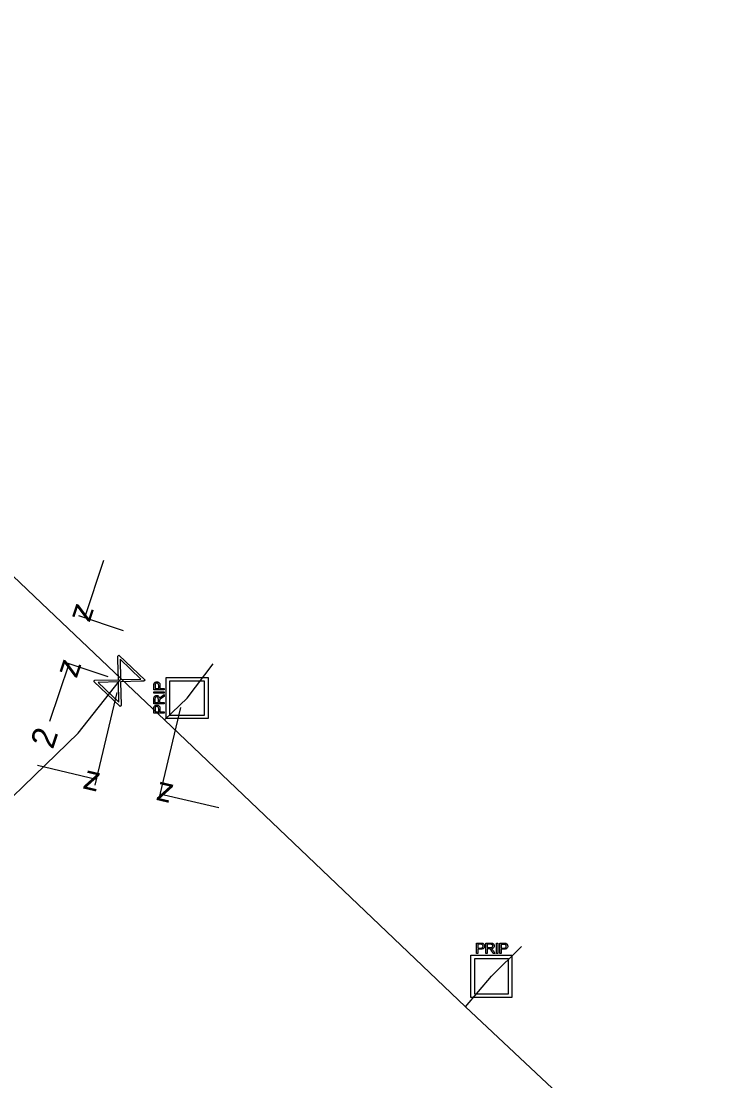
# Model space of a CAD drawing. Extents: x -643842 to -636370, y -1119190 to -1110210.
# Drawn here: x -642410.27 to -642380.97, y -1113929.96 to -1113886.16 of the extents above; entities that cross this region are included whole.
import ezdxf

# ---------------------------------------------------------------- set-up
doc = ezdxf.new("R2010")
doc.units = 0
for name, color, linetype in [('Default', 7, 'Continuous'), ('Level 10', 7, 'Continuous'), ('Level 16', 7, 'Continuous'), ('Level 18', 7, 'Continuous'), ('Level 21', 7, 'Continuous'), ('Level 23', 7, 'Continuous')]:
    doc.layers.add(name, color=color, linetype=linetype)

msp = doc.modelspace()

# ---------------------------------------------------------------- linework, layer by layer
at = {"layer": 'Default'}
for points in [[(-642404.79, -1113913.633), (-642404.79, -1113913.591), (-642404.785, -1113913.567), (-642404.779, -1113913.536), (-642404.765, -1113913.515), (-642404.75, -1113913.493), (-642404.724, -1113913.48), (-642404.697, -1113913.468), (-642404.665, -1113913.468), (-642404.609, -1113913.468), (-642404.572, -1113913.502), (-642404.535, -1113913.536), (-642404.535, -1113913.627)], [(-642404.584, -1113913.627), (-642404.584, -1113913.572), (-642404.605, -1113913.549), (-642404.625, -1113913.526), (-642404.664, -1113913.526), (-642404.69, -1113913.526), (-642404.709, -1113913.539), (-642404.728, -1113913.553), (-642404.734, -1113913.575), (-642404.738, -1113913.589), (-642404.738, -1113913.629)], [(-642404.791, -1113914.182), (-642404.791, -1113914.125), (-642404.779, -1113914.095), (-642404.768, -1113914.065), (-642404.738, -1113914.048), (-642404.709, -1113914.03), (-642404.674, -1113914.03), (-642404.627, -1113914.03), (-642404.596, -1113914.059), (-642404.565, -1113914.089), (-642404.557, -1113914.15), (-642404.545, -1113914.128), (-642404.535, -1113914.117), (-642404.513, -1113914.092), (-642404.478, -1113914.07)], [(-642404.601, -1113914.194), (-642404.601, -1113914.155), (-642404.609, -1113914.133), (-642404.617, -1113914.111), (-642404.634, -1113914.1), (-642404.652, -1113914.089), (-642404.674, -1113914.089), (-642404.703, -1113914.089), (-642404.723, -1113914.111), (-642404.743, -1113914.133), (-642404.743, -1113914.181)], [(-642404.45, -1113914.122), (-642404.489, -1113914.147), (-642404.51, -1113914.163), (-642404.53, -1113914.18), (-642404.538, -1113914.193), (-642404.546, -1113914.206), (-642404.549, -1113914.219), (-642404.552, -1113914.228), (-642404.552, -1113914.25)], [(-642404.791, -1113914.596), (-642404.791, -1113914.553), (-642404.787, -1113914.53), (-642404.781, -1113914.499), (-642404.766, -1113914.477), (-642404.751, -1113914.455), (-642404.725, -1113914.442), (-642404.699, -1113914.43), (-642404.667, -1113914.43), (-642404.611, -1113914.43), (-642404.573, -1113914.464), (-642404.536, -1113914.499), (-642404.536, -1113914.59)], [(-642404.586, -1113914.59), (-642404.586, -1113914.534), (-642404.606, -1113914.511), (-642404.627, -1113914.489), (-642404.665, -1113914.489), (-642404.691, -1113914.489), (-642404.71, -1113914.502), (-642404.73, -1113914.515), (-642404.735, -1113914.537), (-642404.74, -1113914.552), (-642404.74, -1113914.591)], [(-642391.283, -1113924.264), (-642391.24, -1113924.264), (-642391.217, -1113924.268), (-642391.186, -1113924.274), (-642391.164, -1113924.289), (-642391.142, -1113924.304), (-642391.129, -1113924.33), (-642391.117, -1113924.356), (-642391.117, -1113924.388), (-642391.117, -1113924.444), (-642391.151, -1113924.482), (-642391.186, -1113924.519), (-642391.277, -1113924.519)], [(-642391.277, -1113924.469), (-642391.221, -1113924.469), (-642391.198, -1113924.449), (-642391.176, -1113924.428), (-642391.176, -1113924.39), (-642391.176, -1113924.364), (-642391.189, -1113924.345), (-642391.202, -1113924.326), (-642391.224, -1113924.32), (-642391.239, -1113924.315), (-642391.278, -1113924.315)], [(-642390.809, -1113924.605), (-642390.834, -1113924.566), (-642390.85, -1113924.545), (-642390.867, -1113924.525), (-642390.88, -1113924.517), (-642390.893, -1113924.509), (-642390.906, -1113924.506), (-642390.915, -1113924.503), (-642390.937, -1113924.503)], [(-642390.881, -1113924.454), (-642390.842, -1113924.454), (-642390.82, -1113924.446), (-642390.798, -1113924.438), (-642390.787, -1113924.421), (-642390.776, -1113924.403), (-642390.776, -1113924.381), (-642390.776, -1113924.352), (-642390.798, -1113924.332), (-642390.82, -1113924.312), (-642390.868, -1113924.312)], [(-642390.869, -1113924.264), (-642390.812, -1113924.264), (-642390.782, -1113924.276), (-642390.752, -1113924.287), (-642390.735, -1113924.317), (-642390.717, -1113924.346), (-642390.717, -1113924.381), (-642390.717, -1113924.428), (-642390.746, -1113924.459), (-642390.776, -1113924.49), (-642390.837, -1113924.498), (-642390.815, -1113924.51), (-642390.804, -1113924.52), (-642390.779, -1113924.542), (-642390.757, -1113924.577)], [(-642390.32, -1113924.265), (-642390.278, -1113924.265), (-642390.254, -1113924.27), (-642390.223, -1113924.276), (-642390.202, -1113924.29), (-642390.18, -1113924.305), (-642390.167, -1113924.331), (-642390.155, -1113924.358), (-642390.155, -1113924.39), (-642390.155, -1113924.446), (-642390.189, -1113924.483), (-642390.223, -1113924.52), (-642390.314, -1113924.52)], [(-642390.314, -1113924.471), (-642390.259, -1113924.471), (-642390.236, -1113924.45), (-642390.213, -1113924.43), (-642390.213, -1113924.391), (-642390.213, -1113924.365), (-642390.226, -1113924.346), (-642390.24, -1113924.327), (-642390.262, -1113924.321), (-642390.276, -1113924.317), (-642390.316, -1113924.317)]]:
    msp.add_open_spline(points, degree=3, dxfattribs=at)
at = {"layer": 'Level 10'}
for points in [[(-642406.864, -1113908.452), (-642407.66, -1113910.822)], [(-642406.047, -1113911.364), (-642407.897, -1113910.742)], [(-642409.093, -1113915.089), (-642408.297, -1113912.719)], [(-642406.684, -1113913.261), (-642408.534, -1113912.64)], [(-642406.325, -1113913.907), (-642407.224, -1113917.731)], [(-642403.692, -1113914.526), (-642404.592, -1113918.351)], [(-642409.601, -1113916.915), (-642407.167, -1113917.488)], [(-642402.101, -1113918.68), (-642404.535, -1113918.107)]]:
    msp.add_lwpolyline(points, dxfattribs=at)
at = {"layer": 'Level 16'}
for points in [[(-642406.237, -1113912.36), (-642405.15, -1113913.394), (-642405.196, -1113913.441), (-642405.324, -1113913.44), (-642406.164, -1113913.463), (-642406.138, -1113914.433), (-642406.184, -1113914.481), (-642407.271, -1113913.447), (-642407.225, -1113913.399), (-642406.254, -1113913.377), (-642406.276, -1113912.537), (-642406.283, -1113912.408), (-642406.237, -1113912.36)], [(-642406.188, -1113912.536), (-642406.166, -1113913.375), (-642405.329, -1113913.353), (-642406.188, -1113912.536)], [(-642406.23, -1113914.308), (-642406.252, -1113913.465), (-642407.093, -1113913.487), (-642406.23, -1113914.308)]]:
    msp.add_lwpolyline(points, dxfattribs=at)
at = {"layer": 'Level 18'}
for points in [[(-642404.359, -1113913.794), (-642404.79, -1113913.794), (-642404.79, -1113913.633)], [(-642404.738, -1113913.629), (-642404.738, -1113913.739), (-642404.584, -1113913.739)], [(-642404.584, -1113913.739), (-642404.584, -1113913.627)], [(-642404.535, -1113913.627), (-642404.535, -1113913.739), (-642404.359, -1113913.739), (-642404.359, -1113913.794)], [(-642404.284, -1113913.292), (-642402.542, -1113913.292), (-642402.542, -1113914.988), (-642404.284, -1113914.988), (-642404.284, -1113913.292)], [(-642404.136, -1113914.843), (-642402.69, -1113914.843), (-642402.69, -1113913.437), (-642404.136, -1113913.437), (-642404.136, -1113914.843)], [(-642404.359, -1113913.936), (-642404.79, -1113913.936), (-642404.79, -1113913.881), (-642404.359, -1113913.881), (-642404.359, -1113913.936)], [(-642404.478, -1113914.07), (-642404.36, -1113913.995), (-642404.36, -1113914.067), (-642404.45, -1113914.122)], [(-642404.36, -1113914.373), (-642404.791, -1113914.373), (-642404.791, -1113914.182)], [(-642404.743, -1113914.181), (-642404.743, -1113914.316), (-642404.601, -1113914.316)], [(-642404.601, -1113914.316), (-642404.601, -1113914.194)], [(-642404.552, -1113914.25), (-642404.552, -1113914.316), (-642404.36, -1113914.316), (-642404.36, -1113914.373)], [(-642404.36, -1113914.757), (-642404.791, -1113914.757), (-642404.791, -1113914.596)], [(-642404.74, -1113914.591), (-642404.74, -1113914.701), (-642404.586, -1113914.701)], [(-642404.586, -1113914.701), (-642404.586, -1113914.59)], [(-642404.536, -1113914.59), (-642404.536, -1113914.701), (-642404.36, -1113914.701), (-642404.36, -1113914.757)], [(-642391.444, -1113924.695), (-642391.444, -1113924.264), (-642391.283, -1113924.264)], [(-642391.277, -1113924.519), (-642391.388, -1113924.519), (-642391.388, -1113924.695), (-642391.444, -1113924.695)], [(-642391.278, -1113924.315), (-642391.388, -1113924.315), (-642391.388, -1113924.469)], [(-642391.388, -1113924.469), (-642391.277, -1113924.469)], [(-642391.06, -1113924.695), (-642391.06, -1113924.264), (-642390.869, -1113924.264)], [(-642390.937, -1113924.503), (-642391.003, -1113924.503), (-642391.003, -1113924.695), (-642391.06, -1113924.695)], [(-642390.868, -1113924.312), (-642391.003, -1113924.312), (-642391.003, -1113924.454)], [(-642391.003, -1113924.454), (-642390.881, -1113924.454)], [(-642390.757, -1113924.577), (-642390.682, -1113924.695), (-642390.754, -1113924.695), (-642390.809, -1113924.605)], [(-642390.623, -1113924.696), (-642390.623, -1113924.265), (-642390.568, -1113924.265), (-642390.568, -1113924.696), (-642390.623, -1113924.696)], [(-642390.481, -1113924.696), (-642390.481, -1113924.265), (-642390.32, -1113924.265)], [(-642390.314, -1113924.52), (-642390.426, -1113924.52), (-642390.426, -1113924.696), (-642390.481, -1113924.696)], [(-642390.316, -1113924.317), (-642390.426, -1113924.317), (-642390.426, -1113924.471)], [(-642390.426, -1113924.471), (-642390.314, -1113924.471)], [(-642389.979, -1113924.771), (-642389.979, -1113926.513), (-642391.675, -1113926.513), (-642391.675, -1113924.771), (-642389.979, -1113924.771)], [(-642391.53, -1113924.919), (-642391.53, -1113926.365), (-642390.124, -1113926.365), (-642390.124, -1113924.919), (-642391.53, -1113924.919)]]:
    msp.add_lwpolyline(points, dxfattribs=at)
at = {"layer": 'Level 21'}
msp.add_lwpolyline([(-642434.757, -1113886.158), (-642434.32, -1113886.59), (-642432.757, -1113887.981), (-642428.894, -1113891.665), (-642427.355, -1113893.147), (-642421.665, -1113898.587), (-642417.242, -1113902.729), (-642416.765, -1113903.23), (-642412.711, -1113907.096), (-642409.435, -1113910.22), (-642406.138, -1113913.346), (-642404.352, -1113915.036), (-642391.898, -1113926.897), (-642385.4, -1113933.009), (-642382.19, -1113936.174), (-642381.1, -1113937.25), (-642380.97, -1113937.68), (-642381.95, -1113946.17), (-642382.8, -1113955.3), (-642382.85, -1113955.65)], dxfattribs=at)
at = {"layer": 'Level 23'}
for points in [[(-642404.352, -1113915.036), (-642403.417, -1113914.14), (-642402.332, -1113912.727)], [(-642420.861, -1113928.046), (-642417.88, -1113925.24), (-642407.92, -1113915.59), (-642406.21, -1113913.42), (-642406.138, -1113913.346)], [(-642391.898, -1113926.897), (-642390.827, -1113925.638), (-642389.584, -1113924.407)]]:
    msp.add_lwpolyline(points, dxfattribs=at)

# ---------------------------------------------------------------- texts
at = {"layer": 'Level 10'}
for s, rotation, p in [('z', 251.4403, (-642407.975, -1113910.189)), ('z', 71.4403, (-642407.982, -1113913.352)), ('2', 71.4403, (-642408.967, -1113916.287)), ('z', 346.7612, (-642407.768, -1113917.86)), ('z', 166.7612, (-642403.933, -1113917.735))]:
    msp.add_text(s, height=1, rotation=rotation, dxfattribs=at).set_placement(p)

doc.saveas('drawing.dxf')
